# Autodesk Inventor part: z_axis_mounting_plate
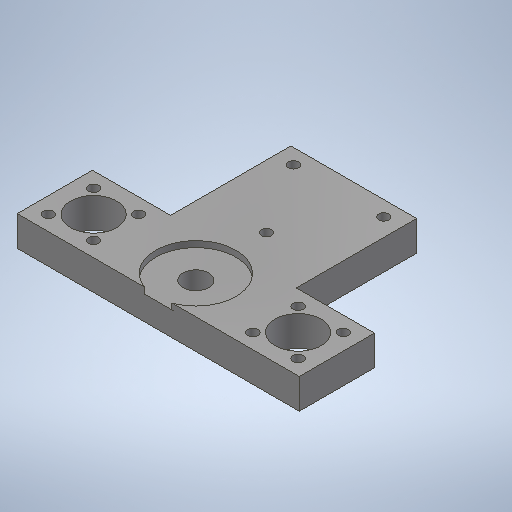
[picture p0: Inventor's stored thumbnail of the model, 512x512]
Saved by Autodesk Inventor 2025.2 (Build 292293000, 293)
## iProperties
Created: 2025-04
Part Number: z_axis_mounting_plate
Material: 1.0037 S235JR
Document SubType Name: Modeling
Designer: BennF
Density: 7.85 g/cm^3
Appearance: Stahl
Author: BennF
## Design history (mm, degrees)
sketch "Sketch2"
  geometry: L1 (-20.9, 65)-(-20.9, 25); L2 (-20.9, 25)-(-46.9, 25); L3 (-46.9, 25)-(-46.9, 0); L4 (-46.9, 0)-(46.9, 0); L5 (46.9, 0)-(46.9, 25); L6 (46.9, 25)-(20.9, 25); L7 (20.9, 25)-(20.9, 65); L8 (20.9, 65)-(-20.9, 65); 3 further points
  constraints: 16 end point, 6 perpendicular, 2 midpoint, 2 point on line, 1 coincident, 1 vertical, 1 vertical alignment
  dimensions: "d0" = 41.8 distance of L7.end L1.start; "d1" = 93.8 distance of L3.end L4.end (computed from d0); "d2" = 40 distance of L6.end L7.end; "d3" = 25 distance of L4.end L5.end
extrude "Extrusion1" new body sketch "Sketch2" distance "d4" = 10; taper "d5" = 0 deg
sketch "Sketch3"
  geometry: L1 (-15, 60)-(15, 60); L2 (46.9, 0)-(-46.9, 0) reference; L3 (-20.9, 65)-(20.9, 65) reference; 4 further points
  constraints: 2 end point, 2 midpoint, 2 vertical alignment, 1 horizontal, 1 horizontal alignment
  dimensions: "d13" = 24 distance from line of point (0, 36) L1; "d14" = 30 distance of L1.start L1.end; "d15" = 5 distance between parallel lines of L3 L1
hole "Hole1" sketch "Sketch3" at (-15, 60), (15, 60), (0, 36) diameter "d6" = 3.4; stored, may be unused: countersink angle "d10" = 90 deg, drill point angle "d12" = 118 deg; dims "d7" = 6, "d8" = 7.5, "d9" = 2, "d11" = 8
sketch "Sketch4"
  geometry: L1 (-34, 12.5)-(34, 12.5); L2 (-46.9, 0)-(46.9, 0) reference; L3 (46.9, 0)-(46.9, 25) reference; C1 r 7.65 at (-34, 12.5); C2 r 7.65 at (34, 12.5); 4 further points
  constraints: 3 midpoint, 2 centre point, 2 end point, 2 horizontal alignment, 1 equal radius, 1 horizontal, 1 vertical alignment
  dimensions: "d16" = 68 distance of L1.start L1.end; "d17" = 15.3 diameter of C2
extrude "Extrusion2" cut sketch "Sketch4" extent not by distance; stored distance "d18" = 0; taper "d19" = 0 deg
sketch "Sketch5"
  geometry: L1 (-46.9, 0)-(46.9, 0) reference; C1 r 4.25 at (0, 12.5); C2 r 7.65 at (34, 12.5) reference; 2 further points
  constraints: 1 centre point, 1 horizontal alignment, 1 midpoint, 1 vertical alignment
  dimensions: "d20" = 8.5 diameter of C1
extrude "Extrusion3" cut sketch "Sketch5" extent not by distance; stored distance "d21" = 0; taper "d22" = 0 deg
sketch "Sketch6"
  geometry: L1 (-41.513, 20.013)-(-26.487, 4.987); L2 (-26.487, 20.013)-(-41.513, 4.987); C1 r 7.65 at (-34, 12.5) reference; C2 r 7.65 at (34, 12.5) reference; A1 r 10.625 centre (-34, 12.5) between (-41.513, 20.013) and (-26.487, 20.013); A2 r 10.625 centre (34, 12.5) between (26.487, 20.013) and (26.487, 4.987); 4 further points
  constraints: 8 point on circle, 6 horizontal alignment, 4 end point, 2 centre point, 2 coincident, 2 midpoint, 2 vertical alignment, 1 equal radius, 1 perpendicular
  dimensions: "d30" = 21.25 diameter of A1
hole "Hole2" sketch "Sketch6" at (-41.513, 20.013), (-26.487, 20.013), (-41.513, 4.987), (-26.487, 4.987), (26.487, 20.013), (41.513, 20.013), (41.513, 4.987), (26.487, 4.987) diameter "d23" = 3.4; stored, may be unused: countersink angle "d27" = 90 deg, drill point angle "d29" = 118 deg; dims "d24" = 6, "d25" = 6.5, "d26" = 3.4, "d28" = 8
sketch "Sketch7"
  geometry: C1 r 4.25 at (0, 12.5) reference; C2 r 13.3 at (0, 12.5); 1 further point
  constraints: 1 centre point, 1 coincident
  dimensions: "d31" = 26.6 diameter of C2
extrude "Extrusion4" cut sketch "Sketch7" distance "d32" = 2; taper "d33" = 0 deg
body "Solid1"
